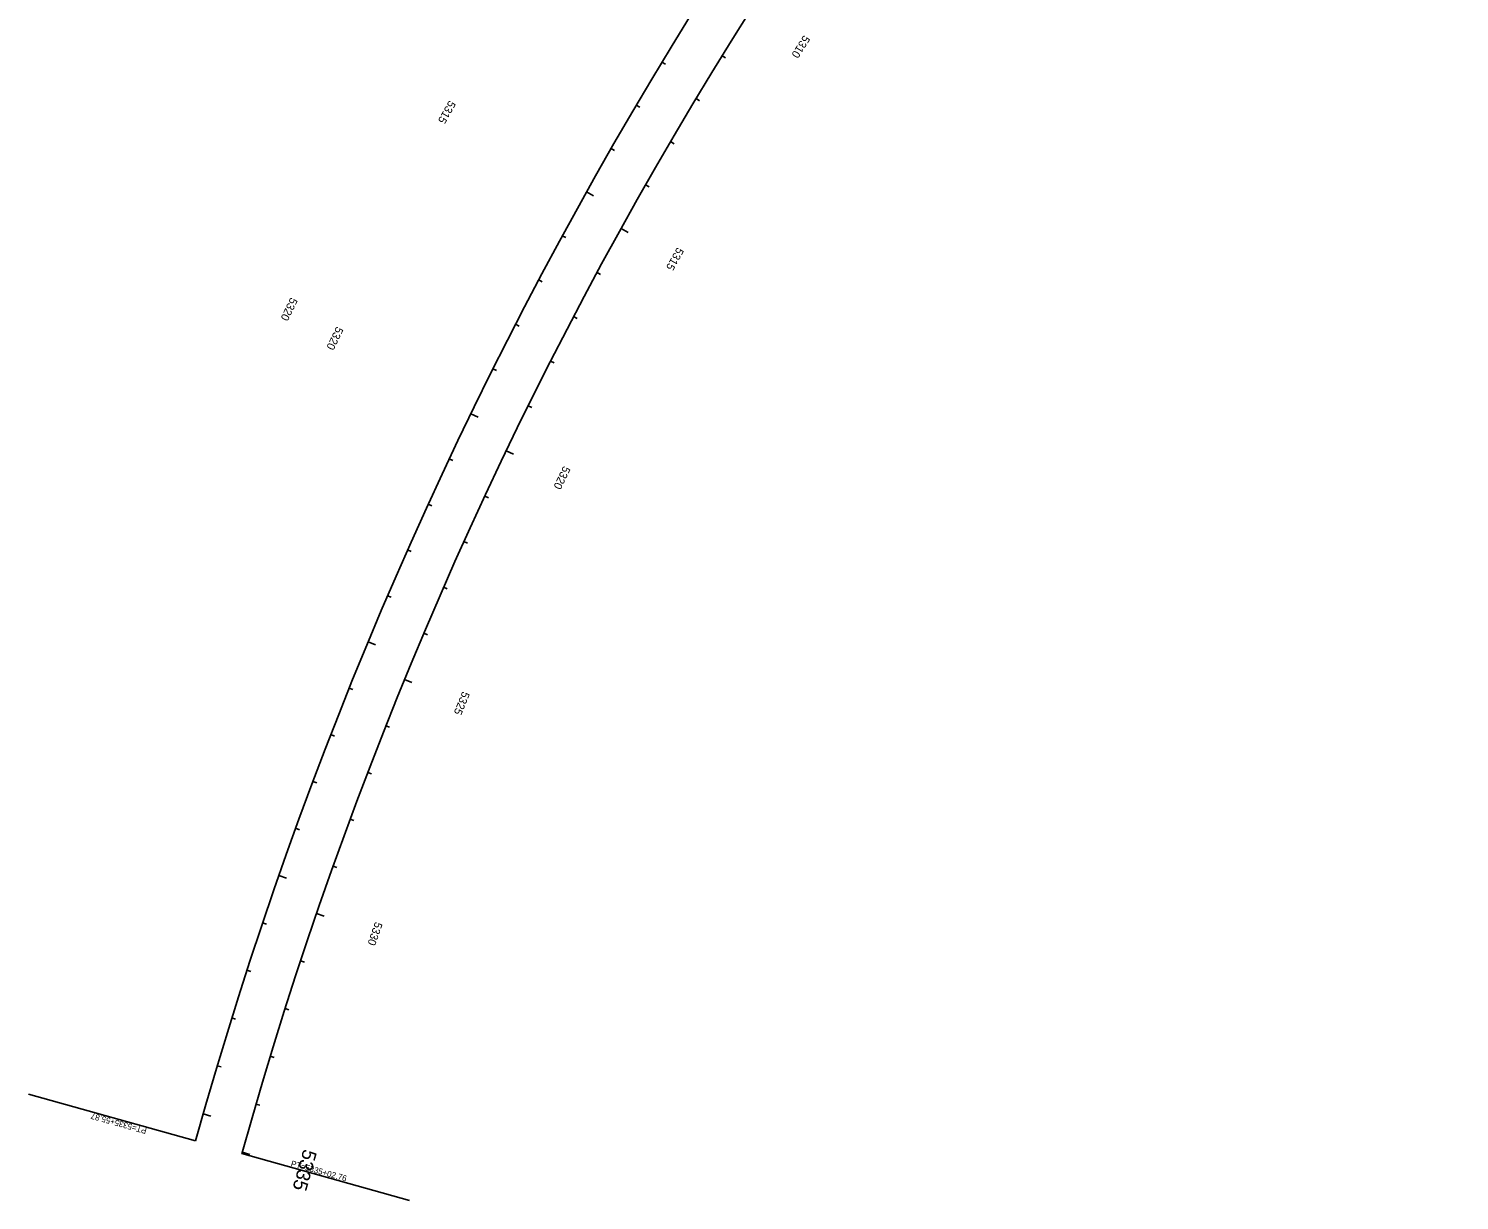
# Model space of a CAD drawing. Extents: x 2160877 to 2175861, y 601747 to 617724.
# Drawn here: x 2160877 to 2163737, y 601747 to 604089 of the extents above; entities that cross this region are included whole.
import ezdxf

# ---------------------------------------------------------------- set-up
doc = ezdxf.new("R2010")
doc.units = 0
for name, color, linetype in [('RD_HC_Cl', 7, 'Continuous'), ('RD_HC_Data', 7, 'Continuous'), ('RD_HC_Data_Tic', 7, 'Continuous'), ('RD_HC_TX_StaOther', 7, 'Continuous')]:
    doc.layers.add(name, color=color, linetype=linetype)

msp = doc.modelspace()

# ---------------------------------------------------------------- linework, layer by layer
at = {"layer": 'RD_HC_Cl'}
for radius in [8641.9, 8545.9]:
    msp.add_arc((2169535, 599544.7), radius, 132.71947, 164.41949, dxfattribs=at)
at = {"layer": 'RD_HC_Data'}
for p, q in [((2161210.6, 601865.9), (2160876.7, 601959)), ((2161303.1, 601840.1), (2161637.9, 601746.8))]:
    msp.add_line(p, q, dxfattribs=at)
at = {"layer": 'RD_HC_Data_Tic'}
for p, q in [((2162263.2, 604034.1), (2162270, 604029.9)), ((2162143, 604021.5), (2162149.8, 604017.3)), ((2162211.2, 603948.7), (2162218, 603944.5)), ((2162091.7, 603935.6), (2162098.6, 603931.6)), ((2162160.2, 603862.7), (2162167.1, 603858.6)), ((2162041.4, 603849.2), (2162048.3, 603845.2)), ((2161992.1, 603762.2), (2162006, 603754.4)), ((2162110.1, 603776.1), (2162117.1, 603772.1)), ((2161943.8, 603674.6), (2161950.8, 603670.8)), ((2162061.1, 603688.9), (2162075.1, 603681.2)), ((2161896.5, 603586.5), (2161903.6, 603582.8)), ((2162013.2, 603601.2), (2162020.2, 603597.4)), ((2161850.2, 603497.9), (2161857.4, 603494.2)), ((2161966.2, 603512.9), (2161973.3, 603509.2)), ((2161805, 603408.7), (2161812.2, 603405.1)), ((2161920.3, 603424), (2161927.4, 603420.4)), ((2161760.8, 603319), (2161775.2, 603312)), ((2161875.4, 603334.7), (2161882.6, 603331.1)), ((2161831.6, 603244.8), (2161846, 603237.9)), ((2161717.7, 603228.8), (2161724.9, 603225.4)), ((2161788.8, 603154.4), (2161796.1, 603151)), ((2161675.6, 603138.1), (2161682.8, 603134.7)), ((2161747.1, 603063.5), (2161754.4, 603060.2)), ((2161634.5, 603046.9), (2161641.8, 603043.6)), ((2161594.5, 602955.2), (2161601.9, 602952.1)), ((2161706.5, 602972.1), (2161713.8, 602968.9)), ((2161555.6, 602863.1), (2161570.4, 602857)), ((2161666.9, 602880.3), (2161674.3, 602877.2)), ((2161628.4, 602788), (2161643.2, 602781.9)), ((2161517.7, 602770.6), (2161525.1, 602767.6)), ((2161591, 602695.3), (2161598.5, 602692.3)), ((2161480.9, 602677.6), (2161488.4, 602674.7)), ((2161445.2, 602584.2), (2161452.7, 602581.4)), ((2161554.7, 602602.1), (2161562.2, 602599.2)), ((2161410.6, 602490.4), (2161418.1, 602487.6)), ((2161519.5, 602508.5), (2161527, 602505.7)), ((2161485.3, 602414.5), (2161492.9, 602411.8)), ((2161377, 602396.2), (2161392.2, 602390.9)), ((2161452.3, 602320.1), (2161467.4, 602314.9)), ((2161344.6, 602301.6), (2161352.2, 602299)), ((2161313.2, 602206.6), (2161320.9, 602204.2)), ((2161420.4, 602225.4), (2161428, 602222.9)), ((2161389.6, 602130.2), (2161397.2, 602127.8)), ((2161283, 602111.3), (2161290.6, 602108.9)), ((2161359.9, 602034.7), (2161367.5, 602032.4)), ((2161253.9, 602015.6), (2161261.5, 602013.4)), ((2161225.8, 601919.7), (2161241.2, 601915.3)), ((2161331.3, 601938.9), (2161339, 601936.7)), ((2161303.8, 601842.8), (2161319.3, 601838.5))]:
    msp.add_line(p, q, dxfattribs=at)

# ---------------------------------------------------------------- texts
at = {"layer": 'RD_HC_Data'}
for s, rotation, p in [('PT=5335+55.87', 164.4195, (2161113.8, 601890.8)), ('PT=5335+02.76', 344.4195, (2161400, 601815.2))]:
    msp.add_text(s, height=12, rotation=rotation, dxfattribs=at).set_placement(p)
at = {"layer": 'RD_HC_TX_StaOther'}
for s, height, rotation, p in [('5310', 16, 237.6399, (2162426.7, 604076.5)), ('5315', 16, 240.7891, (2161717.7, 603946)), ('5315', 16, 240.9921, (2162173.7, 603652.6)), ('5320', 16, 244.0312, (2161400.9, 603552.4)), ('5320', 16, 244.1041, (2161492.4, 603494.2)), ('5320', 16, 244.3443, (2161946.3, 603215.6)), ('5325', 16, 247.6966, (2161744.4, 602765.1)), ('5330', 16, 251.0488, (2161569.6, 602304.5)), ('5335', 28, 254.401, (2161426.5, 601850.6))]:
    msp.add_text(s, height=height, rotation=rotation, dxfattribs=at).set_placement(p)

doc.saveas('drawing.dxf')
